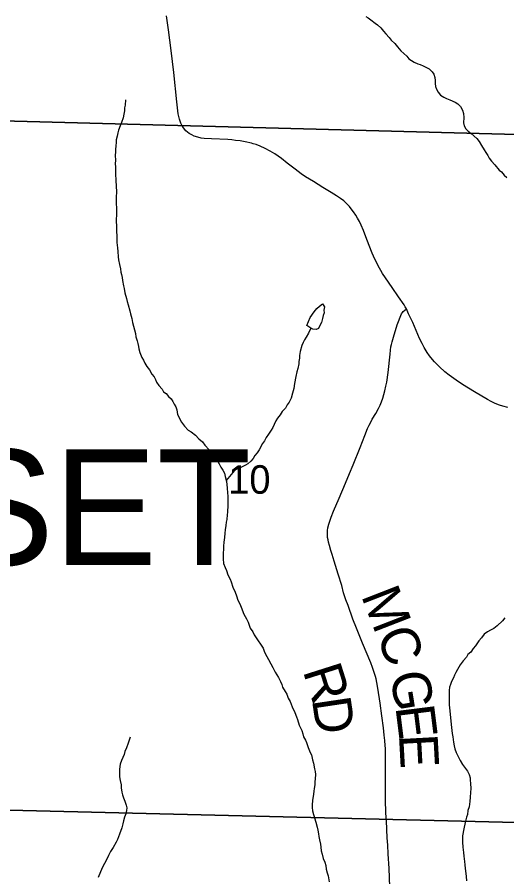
# Model space of a CAD drawing. Extents: x -7.9 to 76.1, y 0 to 22.
# Drawn here: x 3.501 to 4.221, y 15.305 to 16.568 of the extents above; entities that cross this region are included whole.
import ezdxf

# ---------------------------------------------------------------- set-up
doc = ezdxf.new("R2010")
doc.units = 0
for name, color, linetype in [('GM_X_Minor_River', 7, 'Continuous'), ('GM_X_Section', 7, 'Continuous'), ('GM_X_Section_Text', 7, 'Continuous'), ('GM_X_State_Route', 7, 'Continuous'), ('GM_X_Township_Road', 7, 'Continuous'), ('GM_X_Township_Road_Text', 7, 'Continuous'), ('GM_X_Township_Text', 7, 'Continuous')]:
    doc.layers.add(name, color=color, linetype=linetype)

msp = doc.modelspace()

# ---------------------------------------------------------------- linework, layer by layer
at = {"layer": 'GM_X_Minor_River'}
for points in [[(4.0137, 16.5688), (4.0175, 16.567), (4.0214, 16.564), (4.0275, 16.5592), (4.0313, 16.5566), (4.036, 16.5521), (4.0398, 16.5476), (4.0433, 16.5435), (4.0483, 16.5383), (4.0514, 16.5342), (4.0564, 16.5293), (4.0607, 16.5245), (4.0653, 16.5185), (4.0699, 16.5148), (4.0741, 16.5107), (4.0772, 16.5069), (4.0811, 16.5044), (4.0849, 16.5021), (4.0902, 16.4996), (4.094, 16.4985), (4.0982, 16.4967), (4.1024, 16.4945), (4.107, 16.4919), (4.1116, 16.4878), (4.114, 16.4841), (4.1156, 16.4795), (4.116, 16.475), (4.1161, 16.4705), (4.1166, 16.4659), (4.1178, 16.4621), (4.1205, 16.4576), (4.124, 16.4535), (4.1286, 16.4502), (4.1328, 16.4487), (4.1377, 16.4465), (4.1453, 16.4429), (4.1495, 16.4407), (4.1534, 16.4366), (4.1561, 16.4313), (4.1577, 16.4264), (4.1582, 16.4204), (4.1576, 16.4128), (4.1588, 16.4082), (4.1612, 16.4041), (4.1646, 16.4004), (4.1689, 16.397), (4.1773, 16.3896), (4.1808, 16.3851), (4.1839, 16.3795), (4.1878, 16.3731), (4.1905, 16.3693), (4.1933, 16.3645), (4.1956, 16.3607), (4.1987, 16.3566), (4.2037, 16.351), (4.2099, 16.3431), (4.2137, 16.3405), (4.2176, 16.3357), (4.2214, 16.3323)], [(3.6605, 16.4465), (3.6599, 16.4386), (3.6592, 16.4348), (3.6589, 16.4302), (3.6579, 16.4256), (3.6568, 16.4203), (3.6547, 16.4134), (3.6525, 16.4085), (3.6503, 16.402), (3.6493, 16.3982), (3.6482, 16.3932), (3.6468, 16.3879), (3.6465, 16.3841), (3.6462, 16.3784), (3.6459, 16.3742), (3.6456, 16.3693), (3.6453, 16.3655), (3.6455, 16.3571), (3.6451, 16.3533), (3.6456, 16.3469), (3.6458, 16.3348), (3.6463, 16.331), (3.6464, 16.3264), (3.6468, 16.3211), (3.647, 16.3098), (3.6467, 16.3052), (3.6472, 16.2764), (3.6469, 16.2718), (3.6475, 16.2426), (3.6479, 16.2369), (3.6488, 16.229), (3.6493, 16.2237), (3.6498, 16.2157), (3.6503, 16.2116), (3.6515, 16.2048), (3.6532, 16.198), (3.6536, 16.1934), (3.6544, 16.1897), (3.6553, 16.1855), (3.6561, 16.181), (3.6577, 16.1734), (3.6586, 16.1692), (3.6594, 16.1632), (3.6619, 16.1545), (3.6631, 16.1504), (3.6643, 16.1451), (3.6667, 16.1364), (3.6679, 16.1322), (3.6696, 16.1251), (3.6708, 16.1194), (3.6724, 16.1141), (3.6736, 16.1085), (3.6749, 16.1032), (3.6757, 16.0983), (3.6777, 16.0922), (3.6785, 16.0884), (3.6794, 16.0843), (3.6802, 16.0805), (3.6814, 16.0752), (3.6846, 16.0681), (3.6869, 16.0639), (3.6889, 16.0594), (3.6916, 16.0545), (3.6959, 16.0497), (3.699, 16.0437), (3.7025, 16.0396), (3.7044, 16.0354), (3.706, 16.0317), (3.7095, 16.0268), (3.7145, 16.0212), (3.7165, 16.0174), (3.7203, 16.0149), (3.7238, 16.0107), (3.7276, 16.007), (3.7303, 16.0033), (3.7319, 15.9995), (3.7346, 15.9954), (3.7359, 15.9909), (3.7371, 15.9844), (3.7391, 15.9807), (3.741, 15.9765), (3.743, 15.9728), (3.7472, 15.9672), (3.7527, 15.9612), (3.7572, 15.9586), (3.7634, 15.9538), (3.7684, 15.9486), (3.7738, 15.9441), (3.7773, 15.9393), (3.7834, 15.9322), (3.7869, 15.928), (3.79, 15.9228), (3.7962, 15.9153), (3.7982, 15.9116), (3.8009, 15.9067), (3.8036, 15.9026), (3.806, 15.898), (3.8072, 15.8931), (3.8088, 15.8856), (3.8097, 15.8814), (3.8101, 15.8761)], [(3.9271, 16.1148), (3.9322, 16.1266), (3.9381, 16.1351), (3.9421, 16.1397), (3.9459, 16.1436), (3.95, 16.1467), (3.9531, 16.1422), (3.9524, 16.1376), (3.9525, 16.1338), (3.9514, 16.1296), (3.9504, 16.1251), (3.9486, 16.1193), (3.9464, 16.1151), (3.9445, 16.1105), (3.9408, 16.109), (3.9362, 16.1096), (3.9317, 16.1118), (3.9271, 16.1148)], [(3.9332, 16.1111), (3.9295, 16.1038), (3.9262, 16.0977), (3.9236, 16.0939), (3.9218, 16.0901), (3.92, 16.0855), (3.9175, 16.0767), (3.9165, 16.071), (3.9162, 16.0668), (3.9155, 16.0623), (3.9152, 16.0585), (3.9138, 16.052), (3.9124, 16.047), (3.911, 16.0402), (3.9092, 16.0299), (3.9079, 16.0223), (3.9061, 16.0155), (3.904, 16.0082), (3.901, 16.0025), (3.8984, 15.9986), (3.8959, 15.9937), (3.891, 15.9886), (3.8877, 15.9837), (3.884, 15.9787), (3.8818, 15.9748), (3.8793, 15.9695), (3.8771, 15.9653), (3.8749, 15.9614), (3.8708, 15.9553), (3.8675, 15.9503), (3.8649, 15.9457), (3.862, 15.9415), (3.8572, 15.9323), (3.8539, 15.9277), (3.8509, 15.9239), (3.848, 15.9196), (3.8446, 15.9158), (3.8405, 15.9119), (3.8368, 15.9096), (3.8331, 15.9076), (3.8282, 15.9053), (3.8244, 15.9037), (3.8207, 15.9021), (3.8085, 15.8872)], [(3.8101, 15.8761), (3.8106, 15.8693), (3.8111, 15.8644), (3.8109, 15.8568), (3.811, 15.8511), (3.8104, 15.8409), (3.8101, 15.8367), (3.8094, 15.8299), (3.8087, 15.8261), (3.8081, 15.8211), (3.807, 15.8146), (3.8064, 15.8097), (3.8061, 15.8036), (3.8051, 15.7968), (3.8048, 15.7907), (3.8045, 15.7862), (3.8042, 15.7805), (3.8043, 15.7763), (3.804, 15.7721), (3.8045, 15.7653), (3.8069, 15.7593), (3.8088, 15.7552), (3.8112, 15.7484), (3.8144, 15.7424), (3.8159, 15.7382), (3.8183, 15.7307), (3.8219, 15.7232), (3.8235, 15.7179), (3.8255, 15.7115), (3.8286, 15.7062), (3.8306, 15.7013), (3.8346, 15.6908), (3.8385, 15.684), (3.8408, 15.6791), (3.844, 15.6705), (3.8475, 15.6648), (3.8498, 15.6607), (3.8545, 15.6532), (3.8599, 15.6453), (3.8627, 15.6408), (3.865, 15.6352), (3.8682, 15.6288), (3.8709, 15.6243), (3.8744, 15.6179), (3.8772, 15.6127), (3.8807, 15.6055), (3.8857, 15.5976), (3.8885, 15.592), (3.8905, 15.5875), (3.8913, 15.5837), (3.8952, 15.5773), (3.8975, 15.5732), (3.8999, 15.5672), (3.9026, 15.5623), (3.9054, 15.5548), (3.9093, 15.5465), (3.9121, 15.5401), (3.9133, 15.5363), (3.9161, 15.528), (3.9196, 15.5201), (3.9212, 15.5149), (3.9224, 15.5107), (3.9252, 15.5058), (3.9268, 15.5021), (3.9292, 15.4949), (3.9323, 15.4878), (3.9339, 15.484), (3.9355, 15.4768), (3.9371, 15.4719), (3.9384, 15.4636), (3.9392, 15.4595), (3.9397, 15.4553), (3.9394, 15.4488), (3.9387, 15.4443), (3.9388, 15.4401), (3.9381, 15.4348), (3.9375, 15.4306), (3.9368, 15.4264), (3.9354, 15.4169), (3.9348, 15.4109), (3.9348, 15.4067), (3.9353, 15.4018), (3.9369, 15.3965), (3.9405, 15.3852), (3.9425, 15.378), (3.9434, 15.3735), (3.9442, 15.3682), (3.945, 15.3644), (3.9459, 15.3591), (3.9471, 15.3527), (3.9476, 15.3485), (3.9484, 15.3429), (3.9497, 15.3383), (3.9513, 15.3319), (3.9537, 15.3263), (3.9549, 15.3217), (3.9557, 15.3164), (3.9569, 15.3108), (3.9585, 15.3063), (3.9598, 15.2976)], [(4.2183, 15.6857), (4.215, 15.6811), (4.2072, 15.6738), (4.2023, 15.6699), (4.1971, 15.6672), (4.193, 15.6648), (4.1881, 15.6613), (4.184, 15.6563), (4.1803, 15.6517), (4.1752, 15.6444), (4.1718, 15.6406), (4.1685, 15.6352), (4.164, 15.6317), (4.1618, 15.6279), (4.157, 15.6221), (4.1526, 15.6164), (4.1489, 15.6095), (4.1463, 15.6052), (4.1445, 15.6014), (4.1427, 15.5972), (4.1401, 15.5919), (4.1387, 15.5873), (4.1372, 15.5835), (4.1366, 15.5785), (4.1363, 15.5747), (4.1366, 15.5577), (4.137, 15.5531), (4.1379, 15.5437), (4.1397, 15.5289), (4.1411, 15.5157), (4.1419, 15.5104), (4.1428, 15.5028), (4.1437, 15.4972), (4.1449, 15.493), (4.1469, 15.4877), (4.1492, 15.4825), (4.1527, 15.4757), (4.1562, 15.4701), (4.1605, 15.4641), (4.1636, 15.46), (4.166, 15.4551), (4.1672, 15.4506), (4.1676, 15.4468), (4.1681, 15.4419), (4.1682, 15.4347), (4.1679, 15.429), (4.1673, 15.4221), (4.1667, 15.4157), (4.1657, 15.4077), (4.1642, 15.4024), (4.1636, 15.3963), (4.1621, 15.3925), (4.16, 15.3849), (4.1579, 15.3757), (4.1562, 15.3651), (4.1559, 15.3601), (4.1563, 15.356), (4.1565, 15.3484), (4.1569, 15.3446), (4.1577, 15.3405), (4.1582, 15.3355), (4.1591, 15.3276), (4.1596, 15.3227), (4.16, 15.3174), (4.1609, 15.3098), (4.1614, 15.3053), (4.1619, 15.2992)], [(3.6674, 15.51), (3.666, 15.5058), (3.6642, 15.5013), (3.662, 15.4944), (3.6595, 15.489), (3.6584, 15.4849), (3.6566, 15.4803), (3.6544, 15.4757), (3.6526, 15.4707), (3.6519, 15.4669), (3.6516, 15.4627), (3.6518, 15.4521), (3.6526, 15.4465), (3.6539, 15.44), (3.6543, 15.4355), (3.6552, 15.4294), (3.656, 15.4253), (3.6576, 15.4208), (3.6596, 15.4163), (3.6612, 15.4102), (3.6624, 15.4064), (3.6621, 15.4023), (3.6607, 15.3973), (3.6592, 15.3927), (3.6574, 15.3874), (3.6564, 15.3828), (3.655, 15.3771), (3.6517, 15.3676), (3.6503, 15.3638), (3.6488, 15.36), (3.6466, 15.3561), (3.6422, 15.3481), (3.6382, 15.342), (3.6356, 15.3362), (3.6331, 15.3309), (3.6294, 15.3244), (3.6268, 15.319), (3.6239, 15.3125), (3.6203, 15.3041)]]:
    msp.add_lwpolyline(points, dxfattribs=at)
at = {"layer": 'GM_X_Section'}
for points in [[(4.3909, 17.4116), (4.3656, 16.3922), (3.3491, 16.4191), (3.3681, 17.4339)], [(3.3491, 16.4191), (4.3656, 16.3922), (4.3363, 15.3822), (3.3274, 15.4069)], [(4.3363, 15.3822), (4.313, 14.3761), (3.3054, 14.3948), (3.3274, 15.4069)]]:
    msp.add_lwpolyline(points, close=True, dxfattribs=at)
at = {"layer": 'GM_X_State_Route'}
msp.add_lwpolyline([(4.2226, 15.9945), (4.2155, 15.9963), (4.2107, 15.9979), (4.2043, 16.0004), (4.1981, 16.0032), (4.193, 16.006), (4.1738, 16.0174), (4.1562, 16.0281), (4.1468, 16.0346), (4.1363, 16.0422), (4.1301, 16.047), (4.1223, 16.0541), (4.115, 16.0616), (4.1119, 16.0651), (4.1078, 16.0704), (4.1042, 16.0755), (4.0999, 16.0827), (4.0967, 16.0887), (4.0931, 16.0957), (4.0832, 16.1195), (4.0769, 16.1323), (4.0737, 16.1393), (4.0718, 16.1426), (4.0701, 16.1454), (4.0619, 16.1572), (4.0527, 16.1706), (4.0427, 16.1848), (4.0387, 16.1912), (4.0359, 16.1959), (4.0323, 16.2024), (4.03, 16.2069), (4.0273, 16.2124), (4.0234, 16.2212), (4.0154, 16.2411), (4.0104, 16.2547), (4.0072, 16.2622), (4.0044, 16.268), (4.0019, 16.2729), (3.9992, 16.2772), (3.996, 16.2822), (3.9926, 16.2864), (3.9897, 16.2897), (3.9861, 16.2935), (3.9814, 16.2979), (3.9768, 16.3015), (3.971, 16.3054), (3.9631, 16.3103), (3.9505, 16.3179), (3.9369, 16.3263), (3.9253, 16.3335), (3.9189, 16.338), (3.9101, 16.3446), (3.8983, 16.3534), (3.8897, 16.3604), (3.8852, 16.3636), (3.8801, 16.367), (3.8732, 16.3713), (3.866, 16.3751), (3.8586, 16.3785), (3.8526, 16.3809), (3.8483, 16.3821), (3.8459, 16.3827), (3.8363, 16.3849), (3.829, 16.3861), (3.8223, 16.387), (3.8167, 16.3876), (3.8111, 16.388), (3.7871, 16.389), (3.7763, 16.3899), (3.7719, 16.3904), (3.7667, 16.3916), (3.7613, 16.3932), (3.7579, 16.3949), (3.756, 16.3959), (3.7542, 16.3971), (3.7494, 16.4009), (3.7457, 16.4054), (3.7434, 16.4093), (3.742, 16.4122), (3.7408, 16.4152), (3.7399, 16.4182), (3.7381, 16.4259), (3.736, 16.4438), (3.7314, 16.4866), (3.7276, 16.5191), (3.7236, 16.5494), (3.7209, 16.5698)], dxfattribs=at)
at = {"layer": 'GM_X_Township_Road'}
msp.add_lwpolyline([(4.0494, 15.2904), (4.0481, 15.3171), (4.047, 15.3386), (4.0463, 15.3514), (4.0455, 15.3622), (4.0442, 15.387), (4.0436, 15.3983), (4.043, 15.4187), (4.0429, 15.4423), (4.0428, 15.4638), (4.0427, 15.4933), (4.0424, 15.4978), (4.0419, 15.505), (4.0411, 15.5133), (4.0399, 15.5237), (4.0376, 15.5413), (4.035, 15.5603), (4.0317, 15.5819), (4.03, 15.5904), (4.029, 15.5957), (4.0281, 15.5993), (4.0268, 15.6039), (4.0238, 15.6125), (4.0212, 15.6192), (4.0091, 15.6484), (4.0001, 15.6702), (3.9949, 15.6837), (3.9878, 15.7034), (3.9847, 15.7121), (3.9813, 15.7224), (3.9784, 15.733), (3.9733, 15.7496), (3.9674, 15.7686), (3.9643, 15.7783), (3.9623, 15.7846), (3.9603, 15.7916), (3.959, 15.7965), (3.9583, 15.7999), (3.9577, 15.8036), (3.9575, 15.8073), (3.9577, 15.8137), (3.958, 15.8175), (3.9593, 15.823), (3.9628, 15.8336), (3.9663, 15.8422), (3.9747, 15.8614), (3.9839, 15.8831), (3.99, 15.8974), (3.9954, 15.9101), (4.0055, 15.9358), (4.0123, 15.9532), (4.0166, 15.9634), (4.0187, 15.9683), (4.0206, 15.9721), (4.0235, 15.9774), (4.0285, 15.9857), (4.0325, 15.9931), (4.0348, 15.9979), (4.0369, 16.0029), (4.0388, 16.0083), (4.0404, 16.0135), (4.042, 16.0192), (4.0435, 16.0257), (4.0446, 16.0316), (4.0467, 16.0458), (4.0495, 16.0729), (4.0501, 16.0786), (4.0509, 16.0838), (4.0515, 16.0869), (4.0526, 16.0912), (4.0545, 16.0977), (4.0602, 16.1157), (4.0666, 16.132), (4.0677, 16.1339), (4.0689, 16.1354), (4.0737, 16.1393)], dxfattribs=at)

# ---------------------------------------------------------------- texts
at = {"layer": 'GM_X_Section_Text'}
msp.add_text('10', height=0.04186, rotation=0, dxfattribs=at).set_placement((3.8115, 15.8678))
at = {"layer": 'GM_X_Township_Road_Text'}
for s, rotation, p in [('M', 291.2222, (4.0065, 15.7183)), ('C', 290.7127, (4.0288, 15.661)), ('R', 287.6376, (3.9209, 15.6077)), ('G', 279.2713, (4.0494, 15.6034)), ('D', 278.4786, (3.9345, 15.5656)), ('E', 277.1282, (4.0574, 15.5546)), ('E', 273.1129, (4.0626, 15.5135))]:
    msp.add_text(s, height=0.0568, rotation=rotation, dxfattribs=at).set_placement(p)
at = {"layer": 'GM_X_Township_Text'}
msp.add_text('SOMERSET', height=0.17, rotation=0, dxfattribs=at).set_placement((2.5697, 15.7629))

doc.saveas('drawing.dxf')
